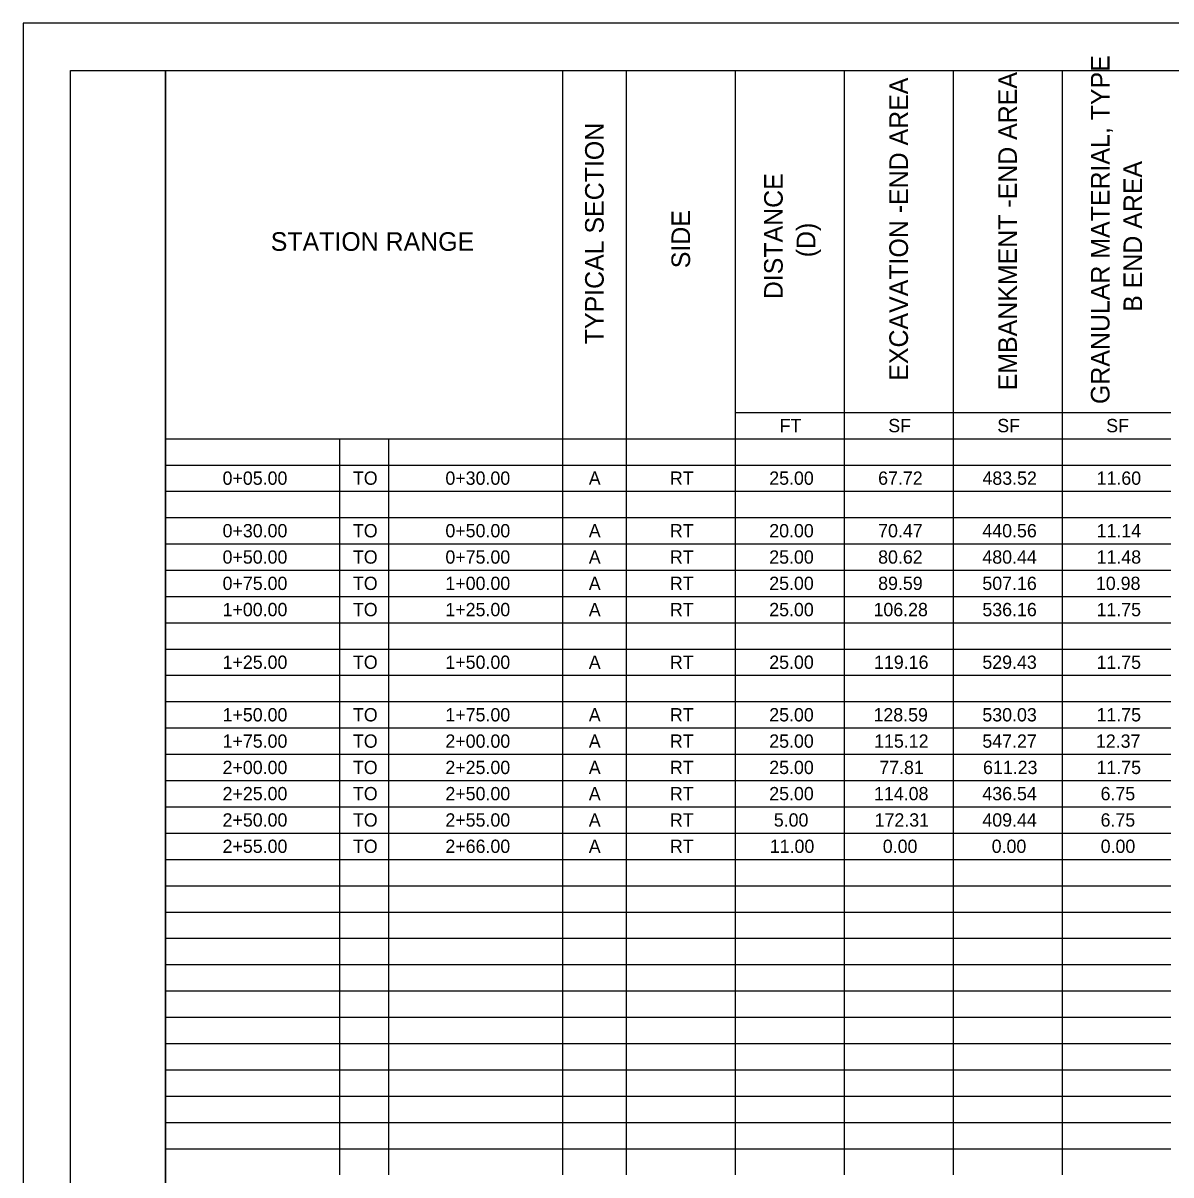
# Model space of a CAD drawing. Extents: x 0 to 34, y 0 to 22.
# Drawn here: x 0 to 12.08, y 9.88 to 22 of the extents above; entities that cross this region are included whole.
import ezdxf

# ---------------------------------------------------------------- set-up
doc = ezdxf.new("R2010")
doc.units = 0
for name, color, linetype in [('Default', 7, 'Continuous'), ('SH_Border', 7, 'Continuous'), ('SH_Cut_Line', 7, 'Continuous')]:
    doc.layers.add(name, color=color, linetype=linetype)

msp = doc.modelspace()

# ---------------------------------------------------------------- linework, layer by layer
at = {"layer": 'Default'}
for p, q in [((1.5, 21.5), (3.845, 21.5)), ((1.5, 21.5), (1.5, 21.223)), ((3.845, 21.5), (8.642, 21.5)), ((5.677, 21.5), (5.677, 21.223)), ((6.349, 21.5), (6.349, 21.223)), ((7.495, 21.5), (7.495, 21.223)), ((8.642, 21.5), (12.081, 21.5)), ((8.642, 21.5), (8.642, 21.223)), ((9.788, 21.5), (9.788, 21.223)), ((10.934, 21.5), (10.934, 21.223)), ((1.5, 21.223), (1.5, 20.947)), ((5.677, 21.223), (5.677, 20.947)), ((6.349, 21.223), (6.349, 20.947)), ((7.495, 21.223), (7.495, 20.947)), ((8.642, 21.223), (8.642, 20.947)), ((9.788, 21.223), (9.788, 20.947)), ((10.934, 21.223), (10.934, 20.947)), ((1.5, 20.947), (1.5, 20.67)), ((5.677, 20.947), (5.677, 20.67)), ((6.349, 20.947), (6.349, 20.67)), ((7.495, 20.947), (7.495, 20.67)), ((8.642, 20.947), (8.642, 20.67)), ((9.788, 20.947), (9.788, 20.67)), ((10.934, 20.947), (10.934, 20.67)), ((1.5, 20.67), (1.5, 20.116)), ((5.677, 20.67), (5.677, 20.116)), ((6.349, 20.67), (6.349, 20.116)), ((7.495, 20.67), (7.495, 20.116)), ((8.642, 20.67), (8.642, 20.116)), ((9.788, 20.67), (9.788, 20.116)), ((10.934, 20.67), (10.934, 20.116)), ((1.5, 20.116), (1.5, 19.84)), ((5.677, 20.116), (5.677, 19.84)), ((6.349, 20.116), (6.349, 19.84)), ((7.495, 20.116), (7.495, 19.84)), ((8.642, 20.116), (8.642, 19.84)), ((9.788, 20.116), (9.788, 19.84)), ((10.934, 20.116), (10.934, 19.84)), ((1.5, 19.84), (1.5, 19.563)), ((5.677, 19.84), (5.677, 19.563)), ((6.349, 19.84), (6.349, 19.563)), ((7.495, 19.84), (7.495, 19.563)), ((8.642, 19.84), (8.642, 19.563)), ((9.788, 19.84), (9.788, 19.563)), ((10.934, 19.84), (10.934, 19.563)), ((1.5, 19.563), (1.5, 19.286)), ((5.677, 19.563), (5.677, 19.286)), ((6.349, 19.563), (6.349, 19.286)), ((7.495, 19.563), (7.495, 19.286)), ((8.642, 19.563), (8.642, 19.286)), ((9.788, 19.563), (9.788, 19.286)), ((10.934, 19.563), (10.934, 19.286)), ((1.5, 19.286), (1.5, 19.01)), ((5.677, 19.286), (5.677, 19.01)), ((6.349, 19.286), (6.349, 19.01)), ((7.495, 19.286), (7.495, 19.01)), ((8.642, 19.286), (8.642, 19.01)), ((9.788, 19.286), (9.788, 19.01)), ((10.934, 19.286), (10.934, 19.01)), ((1.5, 19.01), (1.5, 18.733)), ((5.677, 19.01), (5.677, 18.733)), ((6.349, 19.01), (6.349, 18.733)), ((7.495, 19.01), (7.495, 18.733)), ((8.642, 19.01), (8.642, 18.733)), ((9.788, 19.01), (9.788, 18.733)), ((10.934, 19.01), (10.934, 18.733)), ((1.5, 18.733), (1.5, 18.456)), ((5.677, 18.733), (5.677, 18.456)), ((6.349, 18.733), (6.349, 18.456)), ((7.495, 18.733), (7.495, 18.456)), ((8.642, 18.733), (8.642, 18.456)), ((9.788, 18.733), (9.788, 18.456)), ((10.934, 18.733), (10.934, 18.456)), ((1.5, 18.456), (1.5, 18.18)), ((5.677, 18.456), (5.677, 18.18)), ((6.349, 18.456), (6.349, 18.18)), ((7.495, 18.456), (7.495, 18.18)), ((8.642, 18.456), (8.642, 18.18)), ((9.788, 18.456), (9.788, 18.18)), ((10.934, 18.456), (10.934, 18.18)), ((1.5, 18.18), (1.5, 17.903)), ((5.677, 18.18), (5.677, 17.903)), ((6.349, 18.18), (6.349, 17.903)), ((7.495, 18.18), (7.495, 17.903)), ((8.642, 18.18), (8.642, 17.903)), ((9.788, 18.18), (9.788, 17.903)), ((10.934, 18.18), (10.934, 17.903)), ((1.5, 17.903), (1.5, 17.626)), ((5.677, 17.903), (5.677, 17.626)), ((6.349, 17.903), (6.349, 17.626)), ((7.495, 17.903), (8.642, 17.903)), ((7.495, 17.903), (7.495, 17.626)), ((8.642, 17.903), (12.081, 17.903)), ((8.642, 17.903), (8.642, 17.626)), ((9.788, 17.903), (9.788, 17.626)), ((10.934, 17.903), (10.934, 17.626)), ((1.5, 17.626), (3.845, 17.626)), ((1.5, 17.626), (1.5, 17.349)), ((3.332, 17.626), (3.332, 17.349)), ((3.845, 17.626), (8.642, 17.626)), ((3.845, 17.626), (3.845, 17.349)), ((5.677, 17.626), (5.677, 17.349)), ((6.349, 17.626), (6.349, 17.349)), ((7.495, 17.626), (7.495, 17.349)), ((8.642, 17.626), (12.081, 17.626)), ((8.642, 17.626), (8.642, 17.349)), ((9.788, 17.626), (9.788, 17.349)), ((10.934, 17.626), (10.934, 17.349)), ((1.5, 17.349), (3.845, 17.349)), ((1.5, 17.349), (1.5, 17.073)), ((3.332, 17.349), (3.332, 17.073)), ((3.845, 17.349), (8.642, 17.349)), ((3.845, 17.349), (3.845, 17.073)), ((5.677, 17.349), (5.677, 17.073)), ((6.349, 17.349), (6.349, 17.073)), ((7.495, 17.349), (7.495, 17.073)), ((8.642, 17.349), (12.081, 17.349)), ((8.642, 17.349), (8.642, 17.073)), ((9.788, 17.349), (9.788, 17.073)), ((10.934, 17.349), (10.934, 17.073)), ((1.5, 17.073), (3.845, 17.073)), ((1.5, 17.073), (1.5, 16.796)), ((3.332, 17.073), (3.332, 16.796)), ((3.845, 17.073), (8.642, 17.073)), ((3.845, 17.073), (3.845, 16.796)), ((5.677, 17.073), (5.677, 16.796)), ((6.349, 17.073), (6.349, 16.796)), ((7.495, 17.073), (7.495, 16.796)), ((8.642, 17.073), (12.081, 17.073)), ((8.642, 17.073), (8.642, 16.796)), ((9.788, 17.073), (9.788, 16.796)), ((10.934, 17.073), (10.934, 16.796)), ((1.5, 16.796), (3.845, 16.796)), ((1.5, 16.796), (1.5, 16.243)), ((3.332, 16.796), (3.332, 16.243)), ((3.845, 16.796), (8.642, 16.796)), ((3.845, 16.796), (3.845, 16.243)), ((5.677, 16.796), (5.677, 16.243)), ((6.349, 16.796), (6.349, 16.243)), ((7.495, 16.796), (7.495, 16.243)), ((8.642, 16.796), (12.081, 16.796)), ((8.642, 16.796), (8.642, 16.243)), ((9.788, 16.796), (9.788, 16.243)), ((10.934, 16.796), (10.934, 16.243)), ((1.5, 16.519), (3.845, 16.519)), ((3.845, 16.519), (8.642, 16.519)), ((8.642, 16.519), (12.081, 16.519)), ((1.5, 16.243), (3.845, 16.243)), ((1.5, 16.243), (1.5, 15.966)), ((3.332, 16.243), (3.332, 15.966)), ((3.845, 16.243), (8.642, 16.243)), ((3.845, 16.243), (3.845, 15.966)), ((5.677, 16.243), (5.677, 15.966)), ((6.349, 16.243), (6.349, 15.966)), ((7.495, 16.243), (7.495, 15.966)), ((8.642, 16.243), (12.081, 16.243)), ((8.642, 16.243), (8.642, 15.966)), ((9.788, 16.243), (9.788, 15.966)), ((10.934, 16.243), (10.934, 15.966)), ((1.5, 15.966), (3.845, 15.966)), ((1.5, 15.966), (1.5, 15.689)), ((3.332, 15.966), (3.332, 15.689)), ((3.845, 15.966), (8.642, 15.966)), ((3.845, 15.966), (3.845, 15.689)), ((5.677, 15.966), (5.677, 15.689)), ((6.349, 15.966), (6.349, 15.689)), ((7.495, 15.966), (7.495, 15.689)), ((8.642, 15.966), (12.081, 15.966)), ((8.642, 15.966), (8.642, 15.689)), ((9.788, 15.966), (9.788, 15.689)), ((10.934, 15.966), (10.934, 15.689)), ((1.5, 15.689), (3.845, 15.689)), ((1.5, 15.689), (1.5, 15.412)), ((3.332, 15.689), (3.332, 15.412)), ((3.845, 15.689), (8.642, 15.689)), ((3.845, 15.689), (3.845, 15.412)), ((5.677, 15.689), (5.677, 15.412)), ((6.349, 15.689), (6.349, 15.412)), ((7.495, 15.689), (7.495, 15.412)), ((8.642, 15.689), (12.081, 15.689)), ((8.642, 15.689), (8.642, 15.412)), ((9.788, 15.689), (9.788, 15.412)), ((10.934, 15.689), (10.934, 15.412)), ((1.5, 15.412), (3.845, 15.412)), ((1.5, 15.412), (1.5, 14.859)), ((3.332, 15.412), (3.332, 14.859)), ((3.845, 15.412), (8.642, 15.412)), ((3.845, 15.412), (3.845, 14.859)), ((5.677, 15.412), (5.677, 14.859)), ((6.349, 15.412), (6.349, 14.859)), ((7.495, 15.412), (7.495, 14.859)), ((8.642, 15.412), (12.081, 15.412)), ((8.642, 15.412), (8.642, 14.859)), ((9.788, 15.412), (9.788, 14.859)), ((10.934, 15.412), (10.934, 14.859)), ((1.5, 15.136), (3.845, 15.136)), ((3.845, 15.136), (8.642, 15.136)), ((8.642, 15.136), (12.081, 15.136)), ((1.5, 14.859), (3.845, 14.859)), ((1.5, 14.859), (1.5, 14.582)), ((3.332, 14.859), (3.332, 14.582)), ((3.845, 14.859), (8.642, 14.859)), ((3.845, 14.859), (3.845, 14.582)), ((5.677, 14.859), (5.677, 14.582)), ((6.349, 14.859), (6.349, 14.582)), ((7.495, 14.859), (7.495, 14.582)), ((8.642, 14.859), (12.081, 14.859)), ((8.642, 14.859), (8.642, 14.582)), ((9.788, 14.859), (9.788, 14.582)), ((10.934, 14.859), (10.934, 14.582)), ((1.5, 14.582), (3.845, 14.582)), ((1.5, 14.582), (1.5, 14.306)), ((3.332, 14.582), (3.332, 14.306)), ((3.845, 14.582), (8.642, 14.582)), ((3.845, 14.582), (3.845, 14.306)), ((5.677, 14.582), (5.677, 14.306)), ((6.349, 14.582), (6.349, 14.306)), ((7.495, 14.582), (7.495, 14.306)), ((8.642, 14.582), (12.081, 14.582)), ((8.642, 14.582), (8.642, 14.306)), ((9.788, 14.582), (9.788, 14.306)), ((10.934, 14.582), (10.934, 14.306)), ((1.5, 14.306), (3.845, 14.306)), ((1.5, 14.306), (1.5, 14.029)), ((3.332, 14.306), (3.332, 14.029)), ((3.845, 14.306), (8.642, 14.306)), ((3.845, 14.306), (3.845, 14.029)), ((5.677, 14.306), (5.677, 14.029)), ((6.349, 14.306), (6.349, 14.029)), ((7.495, 14.306), (7.495, 14.029)), ((8.642, 14.306), (12.081, 14.306)), ((8.642, 14.306), (8.642, 14.029)), ((9.788, 14.306), (9.788, 14.029)), ((10.934, 14.306), (10.934, 14.029)), ((1.5, 14.029), (3.845, 14.029)), ((1.5, 14.029), (1.5, 13.199)), ((3.332, 14.029), (3.332, 13.199)), ((3.845, 14.029), (8.642, 14.029)), ((3.845, 14.029), (3.845, 13.199)), ((5.677, 14.029), (5.677, 13.199)), ((6.349, 14.029), (6.349, 13.199)), ((7.495, 14.029), (7.495, 13.199)), ((8.642, 14.029), (12.081, 14.029)), ((8.642, 14.029), (8.642, 13.199)), ((9.788, 14.029), (9.788, 13.199)), ((10.934, 14.029), (10.934, 13.199)), ((1.5, 13.752), (3.845, 13.752)), ((3.845, 13.752), (8.642, 13.752)), ((8.642, 13.752), (12.081, 13.752)), ((1.5, 13.476), (3.845, 13.476)), ((3.845, 13.476), (8.642, 13.476)), ((8.642, 13.476), (12.081, 13.476)), ((1.5, 13.199), (3.845, 13.199)), ((1.5, 13.199), (1.5, 12.922)), ((3.332, 13.199), (3.332, 12.922)), ((3.845, 13.199), (8.642, 13.199)), ((3.845, 13.199), (3.845, 12.922)), ((5.677, 13.199), (5.677, 12.922)), ((6.349, 13.199), (6.349, 12.922)), ((7.495, 13.199), (7.495, 12.922)), ((8.642, 13.199), (12.081, 13.199)), ((8.642, 13.199), (8.642, 12.922)), ((9.788, 13.199), (9.788, 12.922)), ((10.934, 13.199), (10.934, 12.922)), ((1.5, 12.922), (3.845, 12.922)), ((1.5, 12.922), (1.5, 11.815)), ((3.332, 12.922), (3.332, 11.815)), ((3.845, 12.922), (8.642, 12.922)), ((3.845, 12.922), (3.845, 11.815)), ((5.677, 12.922), (5.677, 11.815)), ((6.349, 12.922), (6.349, 11.815)), ((7.495, 12.922), (7.495, 11.815)), ((8.642, 12.922), (12.081, 12.922)), ((8.642, 12.922), (8.642, 11.815)), ((9.788, 12.922), (9.788, 11.815)), ((10.934, 12.922), (10.934, 11.815)), ((1.5, 12.645), (3.845, 12.645)), ((3.845, 12.645), (8.642, 12.645)), ((8.642, 12.645), (12.081, 12.645)), ((1.5, 12.369), (3.845, 12.369)), ((3.845, 12.369), (8.642, 12.369)), ((8.642, 12.369), (12.081, 12.369)), ((1.5, 12.092), (3.845, 12.092)), ((3.845, 12.092), (8.642, 12.092)), ((8.642, 12.092), (12.081, 12.092)), ((1.5, 11.815), (3.845, 11.815)), ((1.5, 11.815), (1.5, 11.539)), ((3.332, 11.815), (3.332, 11.539)), ((3.845, 11.815), (8.642, 11.815)), ((3.845, 11.815), (3.845, 11.539)), ((5.677, 11.815), (5.677, 11.539)), ((6.349, 11.815), (6.349, 11.539)), ((7.495, 11.815), (7.495, 11.539)), ((8.642, 11.815), (12.081, 11.815)), ((8.642, 11.815), (8.642, 11.539)), ((9.788, 11.815), (9.788, 11.539)), ((10.934, 11.815), (10.934, 11.539)), ((1.5, 11.539), (3.845, 11.539)), ((1.5, 11.539), (1.5, 10.432)), ((3.332, 11.539), (3.332, 10.432)), ((3.845, 11.539), (8.642, 11.539)), ((3.845, 11.539), (3.845, 10.432)), ((5.677, 11.539), (5.677, 10.432)), ((6.349, 11.539), (6.349, 10.432)), ((7.495, 11.539), (7.495, 10.432)), ((8.642, 11.539), (12.081, 11.539)), ((8.642, 11.539), (8.642, 10.432)), ((9.788, 11.539), (9.788, 10.432)), ((10.934, 11.539), (10.934, 10.432)), ((1.5, 11.262), (3.845, 11.262)), ((3.845, 11.262), (8.642, 11.262)), ((8.642, 11.262), (12.081, 11.262)), ((1.5, 10.985), (3.845, 10.985)), ((3.845, 10.985), (8.642, 10.985)), ((8.642, 10.985), (12.081, 10.985)), ((1.5, 10.708), (3.845, 10.708)), ((3.845, 10.708), (8.642, 10.708)), ((8.642, 10.708), (12.081, 10.708)), ((1.5, 10.432), (3.845, 10.432)), ((1.5, 10.432), (1.5, 9.878)), ((3.332, 10.432), (3.332, 9.878)), ((3.845, 10.432), (8.642, 10.432)), ((3.845, 10.432), (3.845, 9.878)), ((5.677, 10.432), (5.677, 9.878)), ((6.349, 10.432), (6.349, 9.878)), ((7.495, 10.432), (7.495, 9.878)), ((8.642, 10.432), (12.081, 10.432)), ((8.642, 10.432), (8.642, 9.878)), ((9.788, 10.432), (9.788, 9.878)), ((10.934, 10.432), (10.934, 9.878)), ((1.5, 10.155), (3.845, 10.155)), ((3.845, 10.155), (8.642, 10.155)), ((8.642, 10.155), (12.081, 10.155))]:
    msp.add_line(p, q, dxfattribs=at)
at = {"layer": 'SH_Border'}
for points in [[(0.5, 21.5), (1.5, 21.5), (1.5, 0.5), (0.5, 0.5)], [(1.5, 21.5), (33.5, 21.5), (33.5, 0.5), (1.5, 0.5)]]:
    msp.add_lwpolyline(points, close=True, dxfattribs=at)
at = {"layer": 'SH_Cut_Line'}
msp.add_lwpolyline([(0, 0), (34, 0), (34, 22), (0, 22)], close=True, dxfattribs=at)

# ---------------------------------------------------------------- texts
at = {"layer": 'Default'}
for s, p in [('GRANULAR MATERIAL, TYPE ', (11.434, 17.991)), ('EMBANKMENT -END AREA', (10.459, 18.135)), ('EXCAVATION -END AREA', (9.313, 18.236)), ('TYPICAL SECTION', (6.111, 18.62)), ('B END AREA', (11.777, 18.961)), ('DISTANCE                                                                                                        ', (7.995, 19.094)), ('SIDE', (7.02, 19.42)), ('(D)', (8.338, 19.535))]:
    msp.add_text(s, height=0.196, rotation=90, dxfattribs=at).set_placement(p)
for s, height, p in [('STATION RANGE', 0.196, (2.607, 19.603)), ('FT', 0.14, (7.963, 17.694)), ('SF', 0.14, (9.106, 17.694)), ('SF', 0.14, (10.253, 17.694)), ('SF', 0.14, (11.399, 17.694)), ('0+05.00', 0.14, (2.1, 17.141)), ('TO', 0.14, (3.472, 17.141)), ('0+30.00', 0.14, (4.445, 17.141)), ('A', 0.14, (5.954, 17.141)), ('RT', 0.14, (6.808, 17.141)), ('25.00', 0.14, (7.853, 17.141)), ('67.72', 0.14, (8.999, 17.141)), ('483.52', 0.14, (10.097, 17.141)), ('11.60', 0.14, (11.298, 17.141)), ('0+30.00', 0.14, (2.1, 16.588)), ('TO', 0.14, (3.472, 16.588)), ('0+50.00', 0.14, (4.445, 16.588)), ('20.00', 0.14, (7.853, 16.588)), ('70.47', 0.14, (8.999, 16.588)), ('440.56', 0.14, (10.096, 16.588)), ('A', 0.14, (5.954, 16.588)), ('RT', 0.14, (6.808, 16.588)), ('11.14', 0.14, (11.298, 16.588)), ('0+50.00', 0.14, (2.1, 16.311)), ('TO', 0.14, (3.472, 16.311)), ('0+75.00', 0.14, (4.445, 16.311)), ('A', 0.14, (5.954, 16.311)), ('RT', 0.14, (6.808, 16.311)), ('25.00', 0.14, (7.853, 16.311)), ('80.62', 0.14, (8.999, 16.311)), ('480.44', 0.14, (10.096, 16.311)), ('11.48', 0.14, (11.298, 16.311)), ('0+75.00', 0.14, (2.1, 16.034)), ('TO', 0.14, (3.472, 16.034)), ('1+00.00', 0.14, (4.445, 16.034)), ('A', 0.14, (5.954, 16.034)), ('RT', 0.14, (6.808, 16.034)), ('25.00', 0.14, (7.853, 16.034)), ('89.59', 0.14, (8.999, 16.034)), ('507.16', 0.14, (10.096, 16.034)), ('10.98', 0.14, (11.291, 16.034)), ('1+00.00', 0.14, (2.1, 15.758)), ('TO', 0.14, (3.472, 15.758)), ('1+25.00', 0.14, (4.445, 15.758)), ('A', 0.14, (5.954, 15.758)), ('RT', 0.14, (6.808, 15.758)), ('25.00', 0.14, (7.853, 15.758)), ('106.28', 0.14, (8.95, 15.758)), ('536.16', 0.14, (10.096, 15.758)), ('11.75', 0.14, (11.297, 15.758)), ('1+25.00', 0.14, (2.1, 15.204)), ('TO', 0.14, (3.472, 15.204)), ('1+50.00', 0.14, (4.445, 15.204)), ('A', 0.14, (5.954, 15.204)), ('RT', 0.14, (6.808, 15.204)), ('25.00', 0.14, (7.853, 15.204)), ('119.16', 0.14, (8.956, 15.204)), ('529.43', 0.14, (10.096, 15.204)), ('11.75', 0.14, (11.297, 15.204)), ('1+50.00', 0.14, (2.1, 14.651)), ('TO', 0.14, (3.472, 14.651)), ('1+75.00', 0.14, (4.445, 14.651)), ('A', 0.14, (5.954, 14.651)), ('RT', 0.14, (6.808, 14.651)), ('25.00', 0.14, (7.853, 14.651)), ('128.59', 0.14, (8.95, 14.651)), ('530.03', 0.14, (10.096, 14.651)), ('11.75', 0.14, (11.297, 14.651)), ('1+75.00', 0.14, (2.1, 14.374)), ('TO', 0.14, (3.472, 14.374)), ('2+00.00', 0.14, (4.445, 14.374)), ('A', 0.14, (5.954, 14.374)), ('RT', 0.14, (6.808, 14.374)), ('25.00', 0.14, (7.853, 14.374)), ('115.12', 0.14, (8.957, 14.374)), ('547.27', 0.14, (10.096, 14.374)), ('12.37', 0.14, (11.291, 14.374)), ('2+00.00', 0.14, (2.1, 14.097)), ('TO', 0.14, (3.472, 14.097)), ('2+25.00', 0.14, (4.445, 14.097)), ('A', 0.14, (5.954, 14.097)), ('RT', 0.14, (6.808, 14.097)), ('25.00', 0.14, (7.853, 14.097)), ('77.81', 0.14, (9.011, 14.097)), ('611.23', 0.14, (10.103, 14.097)), ('11.75', 0.14, (11.297, 14.097)), ('2+25.00', 0.14, (2.1, 13.821)), ('TO', 0.14, (3.472, 13.821)), ('2+50.00', 0.14, (4.445, 13.821)), ('A', 0.14, (5.954, 13.821)), ('RT', 0.14, (6.808, 13.821)), ('25.00', 0.14, (7.853, 13.821)), ('114.08', 0.14, (8.956, 13.821)), ('436.54', 0.14, (10.096, 13.821)), ('6.75', 0.14, (11.34, 13.821)), ('2+50.00', 0.14, (2.1, 13.544)), ('TO', 0.14, (3.472, 13.544)), ('2+55.00', 0.14, (4.445, 13.544)), ('A', 0.14, (5.954, 13.544)), ('RT', 0.14, (6.808, 13.544)), ('5.00', 0.14, (7.901, 13.544)), ('172.31', 0.14, (8.962, 13.544)), ('409.44', 0.14, (10.096, 13.544)), ('6.75', 0.14, (11.34, 13.544)), ('2+55.00', 0.14, (2.1, 13.267)), ('TO', 0.14, (3.472, 13.267)), ('2+66.00', 0.14, (4.445, 13.267)), ('A', 0.14, (5.954, 13.267)), ('RT', 0.14, (6.808, 13.267)), ('11.00', 0.14, (7.859, 13.267)), ('0.00', 0.14, (9.048, 13.267)), ('0.00', 0.14, (10.194, 13.267)), ('0.00', 0.14, (11.341, 13.267))]:
    msp.add_text(s, height=height, dxfattribs=at).set_placement(p)

doc.saveas('drawing.dxf')
